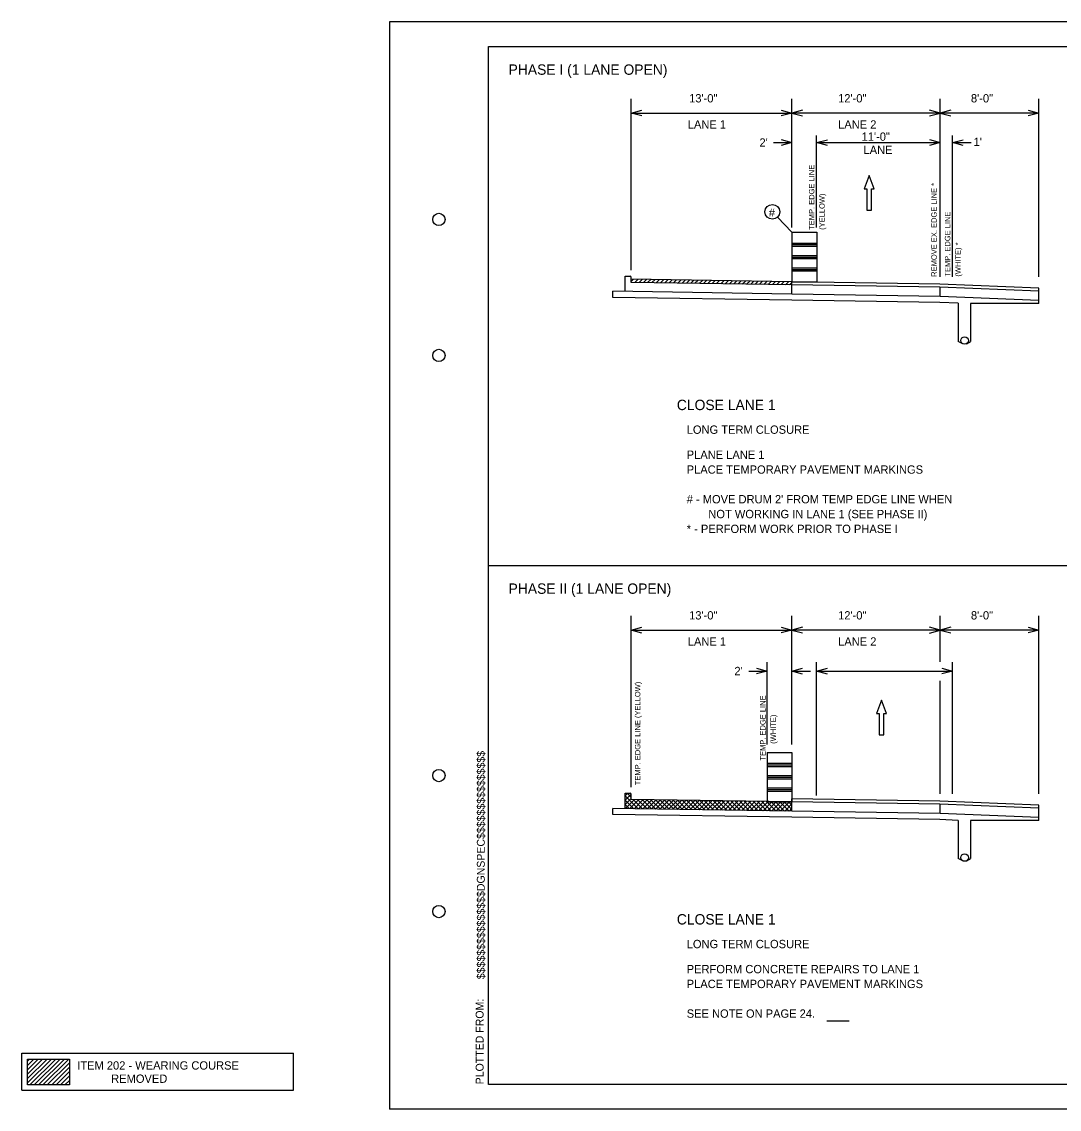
# Model space of a CAD drawing. Extents: x -161 to 291, y -369 to 173.
# Drawn here: x 33.9 to 117.8, y -270.5 to -182.5 of the extents above; entities that cross this region are included whole.
import ezdxf

# ---------------------------------------------------------------- set-up
doc = ezdxf.new("R2010")
doc.units = 0
for name, color, linetype in [('Level 1', 7, 'Continuous'), ('Level 11', 7, 'Continuous'), ('Level 21', 7, 'Continuous'), ('Level 25', 7, 'Continuous'), ('Level 26', 7, 'Continuous'), ('Level 6', 7, 'Continuous'), ('Level 7', 7, 'Continuous')]:
    doc.layers.add(name, color=color, linetype=linetype)

msp = doc.modelspace()

# ---------------------------------------------------------------- linework, layer by layer
at = {"layer": 'Level 1'}
for p, q in [((63.623, -182.503), (63.623, -270.494)), ((199.609, -182.503), (63.623, -182.503)), ((71.623, -184.503), (132.616, -184.503)), ((71.623, -226.499), (71.623, -184.503)), ((71.623, -268.494), (71.623, -226.499)), ((71.623, -226.499), (132.616, -226.499)), ((33.866, -265.949), (55.866, -265.949)), ((33.866, -268.949), (33.866, -265.949)), ((55.866, -268.949), (55.866, -265.949)), ((33.866, -268.949), (55.866, -268.949)), ((197.61, -268.494), (71.623, -268.494)), ((199.609, -270.494), (63.623, -270.494))]:
    msp.add_line(p, q, dxfattribs=at)
for centre in [(67.623, -198.502), (67.623, -209.5), (67.623, -243.497), (67.623, -254.496)]:
    msp.add_circle(centre, 0.5, dxfattribs=at)
at = {"layer": 'Level 11'}
for p, q in [((82.688, -204.328), (82.688, -203.088)), ((82.688, -203.088), (83.105, -203.088)), ((83.188, -203.588), (83.188, -203.171)), ((96.188, -203.539), (83.188, -203.338)), ((83.188, -203.52), (83.368, -203.341)), ((96.188, -203.789), (83.188, -203.588)), ((83.47, -203.592), (83.716, -203.346)), ((83.818, -203.598), (84.064, -203.352)), ((84.166, -203.603), (84.412, -203.357)), ((84.514, -203.609), (84.76, -203.362)), ((84.862, -203.614), (85.108, -203.368)), ((85.21, -203.619), (85.457, -203.373)), ((85.559, -203.625), (85.805, -203.378)), ((85.907, -203.63), (86.153, -203.384)), ((86.255, -203.635), (86.501, -203.389)), ((86.603, -203.641), (86.849, -203.395)), ((86.951, -203.646), (87.197, -203.4)), ((87.299, -203.652), (87.546, -203.405)), ((87.648, -203.657), (87.894, -203.411)), ((87.996, -203.662), (88.242, -203.416)), ((88.344, -203.668), (88.59, -203.421)), ((88.692, -203.673), (88.938, -203.427)), ((89.04, -203.678), (89.287, -203.432)), ((89.388, -203.684), (89.635, -203.438)), ((89.737, -203.689), (89.983, -203.443)), ((90.085, -203.695), (90.331, -203.448)), ((90.433, -203.7), (90.679, -203.454)), ((90.781, -203.705), (91.027, -203.459)), ((91.129, -203.711), (91.376, -203.465)), ((91.478, -203.716), (91.724, -203.47)), ((91.826, -203.721), (92.072, -203.475)), ((92.174, -203.727), (92.42, -203.481)), ((92.522, -203.732), (92.768, -203.486)), ((92.87, -203.738), (93.116, -203.491)), ((93.218, -203.743), (93.465, -203.497)), ((93.567, -203.748), (93.813, -203.502)), ((93.915, -203.754), (94.161, -203.508)), ((94.263, -203.759), (94.509, -203.513)), ((94.611, -203.765), (94.857, -203.518)), ((94.959, -203.77), (95.205, -203.524)), ((95.307, -203.775), (95.554, -203.529)), ((95.656, -203.781), (95.902, -203.534)), ((96.004, -203.786), (96.188, -203.602)), ((96.188, -203.789), (96.188, -203.539)), ((108.164, -203.974), (96.188, -203.789)), ((96.188, -204.537), (96.188, -203.789)), ((108.161, -203.724), (96.192, -203.539)), ((116.161, -204.059), (108.161, -203.724)), ((116.161, -204.309), (108.164, -203.974)), ((108.188, -204.723), (108.188, -203.974)), ((116.161, -205.306), (116.161, -204.059)), ((96.173, -204.537), (81.687, -204.313)), ((96.172, -205.036), (81.687, -204.813)), ((81.688, -204.813), (81.688, -204.313)), ((108.181, -204.722), (96.188, -204.537)), ((116.158, -205.056), (108.181, -204.722)), ((108.163, -205.222), (96.174, -205.036)), ((109.636, -205.283), (108.163, -205.222)), ((109.639, -205.284), (109.639, -208.375)), ((110.639, -205.287), (110.639, -208.364)), ((116.161, -205.306), (110.639, -205.287)), ((110.026, -208.567), (109.639, -208.375)), ((110.316, -208.556), (110.639, -208.364)), ((82.688, -246.164), (82.688, -244.924)), ((82.688, -244.924), (83.105, -244.924)), ((83.188, -245.424), (83.188, -245.007)), ((96.188, -245.625), (83.188, -245.424)), ((96.188, -245.625), (96.188, -245.375)), ((108.161, -245.56), (96.192, -245.375)), ((96.173, -246.372), (81.687, -246.149)), ((81.688, -246.648), (81.688, -246.149)), ((108.164, -245.81), (96.188, -245.625)), ((96.188, -246.373), (96.188, -245.625)), ((108.181, -246.558), (96.188, -246.373)), ((116.161, -245.895), (108.161, -245.56)), ((116.161, -246.145), (108.164, -245.81)), ((108.188, -246.558), (108.188, -245.81)), ((116.161, -247.142), (116.161, -245.895)), ((96.172, -246.872), (81.687, -246.648)), ((108.163, -247.058), (96.174, -246.872)), ((109.636, -247.119), (108.163, -247.058)), ((116.158, -246.892), (108.181, -246.558)), ((109.639, -247.119), (109.639, -250.211)), ((110.639, -247.123), (110.639, -250.2)), ((116.161, -247.142), (110.639, -247.123)), ((110.026, -250.403), (109.639, -250.211)), ((110.316, -250.392), (110.639, -250.2)), ((34.328, -266.597), (34.495, -266.43)), ((34.328, -266.951), (34.849, -266.43)), ((34.328, -267.304), (35.203, -266.43)), ((34.328, -267.658), (35.556, -266.43)), ((34.328, -268.011), (35.91, -266.43)), ((34.328, -268.365), (36.263, -266.43)), ((34.52, -268.527), (36.617, -266.43)), ((34.873, -268.527), (36.97, -266.43)), ((35.227, -268.527), (37.323, -266.43)), ((35.58, -268.527), (37.677, -266.43)), ((35.934, -268.527), (37.72, -266.741)), ((36.288, -268.527), (37.72, -267.095)), ((36.641, -268.527), (37.72, -267.448)), ((36.995, -268.527), (37.72, -267.802)), ((37.348, -268.527), (37.72, -268.155))]:
    msp.add_line(p, q, dxfattribs=at)
for centre in [(110.161, -208.294), (110.161, -250.13)]:
    msp.add_circle(centre, 0.304, dxfattribs=at)
for centre in [(83.105, -203.171), (83.105, -245.007)]:
    msp.add_arc(centre, 0.083, 0, 90, dxfattribs=at)
at = {"layer": 'Level 21'}
for p, q in [((82.688, -245.139), (82.903, -244.924)), ((82.688, -245.493), (83.187, -244.994)), ((82.688, -245.123), (83.746, -246.181)), ((82.688, -245.846), (83.188, -245.346)), ((82.688, -245.476), (83.387, -246.175)), ((82.723, -246.165), (83.46, -245.428)), ((82.843, -244.924), (83.188, -245.269)), ((83.071, -246.17), (83.808, -245.434)), ((83.345, -245.426), (84.105, -246.186)), ((83.42, -246.176), (84.156, -245.439)), ((83.704, -245.432), (84.464, -246.192)), ((83.768, -246.181), (84.504, -245.444)), ((84.063, -245.437), (84.823, -246.197)), ((84.116, -246.186), (84.852, -245.45)), ((84.423, -245.443), (85.182, -246.203)), ((84.464, -246.192), (85.201, -245.455)), ((84.782, -245.449), (85.541, -246.208)), ((84.812, -246.197), (85.549, -245.46)), ((85.141, -245.454), (85.9, -246.214)), ((85.16, -246.202), (85.897, -245.466)), ((85.5, -245.46), (86.26, -246.219)), ((85.509, -246.208), (86.245, -245.471)), ((85.857, -246.213), (86.593, -245.477)), ((85.859, -245.465), (86.619, -246.225)), ((86.205, -246.219), (86.942, -245.482)), ((86.218, -245.471), (86.978, -246.23)), ((86.553, -246.224), (87.29, -245.487)), ((86.577, -245.476), (87.337, -246.236)), ((86.901, -246.229), (87.638, -245.493)), ((86.936, -245.482), (87.696, -246.242)), ((87.295, -245.487), (88.055, -246.247)), ((87.654, -245.493), (88.414, -246.253)), ((82.688, -245.83), (83.028, -246.169)), ((87.249, -246.235), (87.986, -245.498)), ((87.598, -246.24), (88.334, -245.503)), ((87.946, -246.245), (88.682, -245.509)), ((88.014, -245.499), (88.773, -246.258)), ((88.294, -246.251), (89.031, -245.514)), ((88.373, -245.504), (89.132, -246.264)), ((88.642, -246.256), (89.379, -245.52)), ((88.732, -245.51), (89.491, -246.269)), ((88.99, -246.262), (89.727, -245.525)), ((89.091, -245.515), (89.851, -246.275)), ((89.339, -246.267), (90.075, -245.53)), ((89.45, -245.521), (90.21, -246.28)), ((89.687, -246.272), (90.423, -245.536)), ((89.809, -245.526), (90.569, -246.286)), ((90.035, -246.278), (90.771, -245.541)), ((90.168, -245.532), (90.928, -246.291)), ((90.383, -246.283), (91.12, -245.546)), ((90.527, -245.537), (91.287, -246.297)), ((90.731, -246.288), (91.468, -245.552)), ((90.886, -245.543), (91.646, -246.303)), ((91.079, -246.294), (91.816, -245.557)), ((91.245, -245.548), (92.005, -246.308)), ((91.428, -246.299), (92.164, -245.563)), ((91.605, -245.554), (92.364, -246.314)), ((91.776, -246.305), (92.512, -245.568)), ((91.964, -245.56), (92.723, -246.319)), ((92.124, -246.31), (92.86, -245.573)), ((92.323, -245.565), (93.082, -246.325)), ((92.472, -246.315), (93.209, -245.579)), ((92.682, -245.571), (93.442, -246.33)), ((92.82, -246.321), (93.557, -245.584)), ((93.041, -245.576), (93.801, -246.336)), ((93.168, -246.326), (93.905, -245.59)), ((93.4, -245.582), (94.16, -246.341)), ((93.517, -246.331), (94.253, -245.595)), ((93.759, -245.587), (94.519, -246.347)), ((93.865, -246.337), (94.601, -245.6)), ((94.118, -245.593), (94.878, -246.352)), ((94.213, -246.342), (94.95, -245.606)), ((94.477, -245.598), (95.237, -246.358)), ((94.561, -246.348), (95.298, -245.611)), ((94.836, -245.604), (95.596, -246.364)), ((94.909, -246.353), (95.646, -245.616)), ((95.196, -245.609), (95.955, -246.369)), ((95.258, -246.358), (95.994, -245.622)), ((95.555, -245.615), (96.188, -246.248)), ((95.606, -246.364), (96.188, -245.781)), ((95.914, -245.621), (96.188, -245.895)), ((95.954, -246.369), (96.188, -246.135))]:
    msp.add_line(p, q, dxfattribs=at)
at = {"layer": 'Level 25'}
for p, q in [((96.192, -199.539), (96.192, -203.539)), ((96.192, -199.539), (98.192, -199.539)), ((98.192, -199.539), (98.192, -203.539)), ((96.192, -200.414), (98.192, -200.414)), ((96.192, -200.539), (98.192, -200.539)), ((96.192, -200.664), (98.192, -200.664)), ((96.192, -201.414), (98.192, -201.414)), ((96.192, -201.539), (98.192, -201.539)), ((96.192, -201.664), (98.192, -201.664)), ((96.192, -202.414), (98.192, -202.414)), ((96.192, -202.539), (98.192, -202.539)), ((96.192, -202.664), (98.192, -202.664)), ((96.192, -203.539), (98.192, -203.539)), ((94.188, -241.625), (94.188, -245.625)), ((94.188, -241.625), (96.188, -241.625)), ((96.188, -241.625), (96.188, -245.625)), ((94.188, -242.5), (96.188, -242.5)), ((94.188, -242.625), (96.188, -242.625)), ((94.188, -242.75), (96.188, -242.75)), ((94.188, -243.5), (96.188, -243.5)), ((94.188, -243.625), (96.188, -243.625)), ((94.188, -243.75), (96.188, -243.75)), ((94.188, -244.5), (96.188, -244.5)), ((94.188, -244.625), (96.188, -244.625)), ((94.188, -244.75), (96.188, -244.75)), ((94.188, -245.625), (96.188, -245.625))]:
    msp.add_line(p, q, dxfattribs=at)
at = {"layer": 'Level 26'}
for p, q in [((83.188, -202.611), (83.188, -188.729)), ((96.188, -199.151), (96.188, -188.729)), ((108.188, -203.142), (108.188, -188.729)), ((116.161, -203.14), (116.161, -188.729)), ((83.188, -189.888), (96.188, -189.888)), ((108.188, -189.888), (96.188, -189.888)), ((116.161, -189.888), (108.188, -189.888)), ((98.188, -199.151), (98.188, -191.708)), ((109.188, -203.142), (109.188, -191.708)), ((94.688, -192.283), (96.188, -192.283)), ((98.188, -192.283), (108.188, -192.283)), ((109.188, -192.283), (110.688, -192.283)), ((96.192, -199.539), (95.024, -198.304)), ((83.188, -244.447), (83.188, -230.565)), ((96.188, -240.986), (96.188, -230.565)), ((108.188, -234.3), (108.188, -230.565)), ((116.161, -244.976), (116.161, -230.565)), ((83.188, -231.724), (96.188, -231.724)), ((108.188, -231.724), (96.188, -231.724)), ((116.161, -231.724), (108.188, -231.724)), ((94.188, -240.986), (94.188, -234.333)), ((98.188, -245.107), (98.188, -234.333)), ((109.188, -244.978), (109.188, -234.333)), ((92.688, -235.045), (94.188, -235.045)), ((96.188, -235.045), (97.688, -235.045)), ((98.188, -235.045), (109.188, -235.045)), ((108.188, -244.978), (108.188, -235.821))]:
    msp.add_line(p, q, dxfattribs=at)
for points in [[(84.054, -190.128), (83.188, -189.888), (84.054, -189.657)], [(95.322, -189.649), (96.188, -189.888), (95.322, -190.119)], [(97.054, -189.649), (96.188, -189.888), (97.054, -190.119)], [(107.32, -190.128), (108.188, -189.888), (107.32, -189.657)], [(109.054, -189.649), (108.188, -189.888), (109.054, -190.119)], [(115.293, -189.648), (116.161, -189.888), (115.293, -190.12)], [(95.322, -192.044), (96.188, -192.283), (95.322, -192.514)], [(99.054, -192.523), (98.188, -192.283), (99.054, -192.052)], [(107.322, -192.044), (108.188, -192.283), (107.322, -192.514)], [(110.054, -192.523), (109.188, -192.283), (110.054, -192.052)], [(84.054, -231.963), (83.188, -231.724), (84.054, -231.493)], [(95.322, -231.485), (96.188, -231.724), (95.322, -231.955)], [(97.054, -231.485), (96.188, -231.724), (97.054, -231.955)], [(107.32, -231.964), (108.188, -231.724), (107.32, -231.493)], [(109.054, -231.485), (108.188, -231.724), (109.054, -231.955)], [(115.293, -231.484), (116.161, -231.724), (115.293, -231.956)], [(93.322, -234.805), (94.188, -235.045), (93.322, -235.276)], [(97.054, -235.284), (96.188, -235.045), (97.054, -234.814)], [(99.054, -235.284), (98.188, -235.045), (99.054, -234.814)], [(108.322, -234.805), (109.188, -235.045), (108.322, -235.276)]]:
    msp.add_lwpolyline(points, dxfattribs=at)
msp.add_circle((94.602, -197.882), 0.597, dxfattribs=at)
at = {"layer": 'Level 6'}
msp.add_line((99.014, -263.352), (100.822, -263.352), dxfattribs=at)
msp.add_lwpolyline([(34.328, -266.43), (37.72, -266.43), (37.72, -268.527), (34.328, -268.527)], close=True, dxfattribs=at)
at = {"layer": 'Level 7'}
for p, q in [((102.435, -194.938), (102.038, -196.009)), ((102.837, -196.009), (102.435, -194.938)), ((102.038, -196.009), (102.243, -196.009)), ((102.243, -196.009), (102.243, -197.736)), ((102.632, -197.736), (102.632, -196.009)), ((102.632, -196.009), (102.837, -196.009)), ((102.243, -197.736), (102.632, -197.736)), ((103.426, -237.402), (103.029, -238.473)), ((103.828, -238.473), (103.426, -237.402)), ((103.029, -238.473), (103.234, -238.473)), ((103.234, -238.473), (103.234, -240.2)), ((103.623, -240.2), (103.623, -238.473)), ((103.623, -238.473), (103.828, -238.473)), ((103.234, -240.2), (103.623, -240.2))]:
    msp.add_line(p, q, dxfattribs=at)

# ---------------------------------------------------------------- texts
at = {"layer": 'Level 1'}
for s, p in [('$$$$$$$$$$$$$$$DGNSPEC$$$$$$$$$$$$$$$', (71.332, -259.971)), ('PLOTTED FROM:', (71.236, -268.48))]:
    msp.add_text(s, height=0.63859, rotation=90, dxfattribs=at).set_placement(p)
at = {"layer": 'Level 26'}
for s, p in [('13\'-0"', (87.869, -189.031)), ('12\'-0"', (99.926, -189.031)), ('8\'-0"', (110.672, -189.031)), ('LANE 1', (87.759, -191.147)), ('LANE 2', (99.926, -191.147)), ('11\'-0"', (101.825, -192.134)), ("2'", (93.559, -192.611)), ('LANE', (101.98, -193.206)), ("1'", (110.89, -192.56)), ('#', (94.318, -198.284)), ('13\'-0"', (87.869, -230.867)), ('12\'-0"', (99.926, -230.867)), ('8\'-0"', (110.672, -230.867)), ('LANE 1', (87.759, -232.983)), ('LANE 2', (99.926, -232.983)), ("2'", (91.533, -235.372))]:
    msp.add_text(s, height=0.672, dxfattribs=at).set_placement(p)
for s, p in [('TEMP. EDGE LINE', (98.003, -199.339)), ('REMOVE EX. EDGE LINE *', (107.905, -203.142)), ('(YELLOW) ', (98.843, -199.339)), ('TEMP. EDGE LINE', (109.002, -203.128)), ('(WHITE) *', (109.842, -203.128)), ('TEMP. EDGE LINE (YELLOW) ', (83.923, -244.276)), ('TEMP. EDGE LINE', (94.053, -242.279)), ('        (WHITE) ', (94.893, -242.279))]:
    msp.add_text(s, height=0.44, rotation=90, dxfattribs=at).set_placement(p)
at = {"layer": 'Level 6'}
for s, height, p in [('PHASE I (1 LANE OPEN)', 0.84, (73.256, -186.794)), ('CLOSE LANE 1', 0.84, (86.874, -213.927)), ('LONG TERM CLOSURE', 0.672, (87.674, -215.843)), ('PLANE LANE 1 ', 0.672, (87.674, -217.871)), ('PLACE TEMPORARY PAVEMENT MARKINGS', 0.672, (87.674, -219.071)), ("# - MOVE DRUM 2' FROM TEMP EDGE LINE WHEN", 0.672, (87.674, -221.471)), ('       NOT WORKING IN LANE 1 (SEE PHASE II)', 0.672, (87.674, -222.671)), ('* - PERFORM WORK PRIOR TO PHASE I', 0.672, (87.674, -223.871)), ('PHASE II (1 LANE OPEN)', 0.84, (73.256, -228.79)), ('CLOSE LANE 1', 0.84, (86.874, -255.546)), ('LONG TERM CLOSURE', 0.672, (87.674, -257.462)), ('PERFORM CONCRETE REPAIRS TO LANE 1', 0.672, (87.674, -259.49)), ('PLACE TEMPORARY PAVEMENT MARKINGS', 0.672, (87.674, -260.69)), ('SEE NOTE ON PAGE 24.', 0.672, (87.674, -263.09)), ('ITEM 202 - WEARING COURSE', 0.672, (38.356, -267.285)), ('           REMOVED', 0.672, (38.356, -268.357))]:
    msp.add_text(s, height=height, dxfattribs=at).set_placement(p)

doc.saveas('drawing.dxf')
